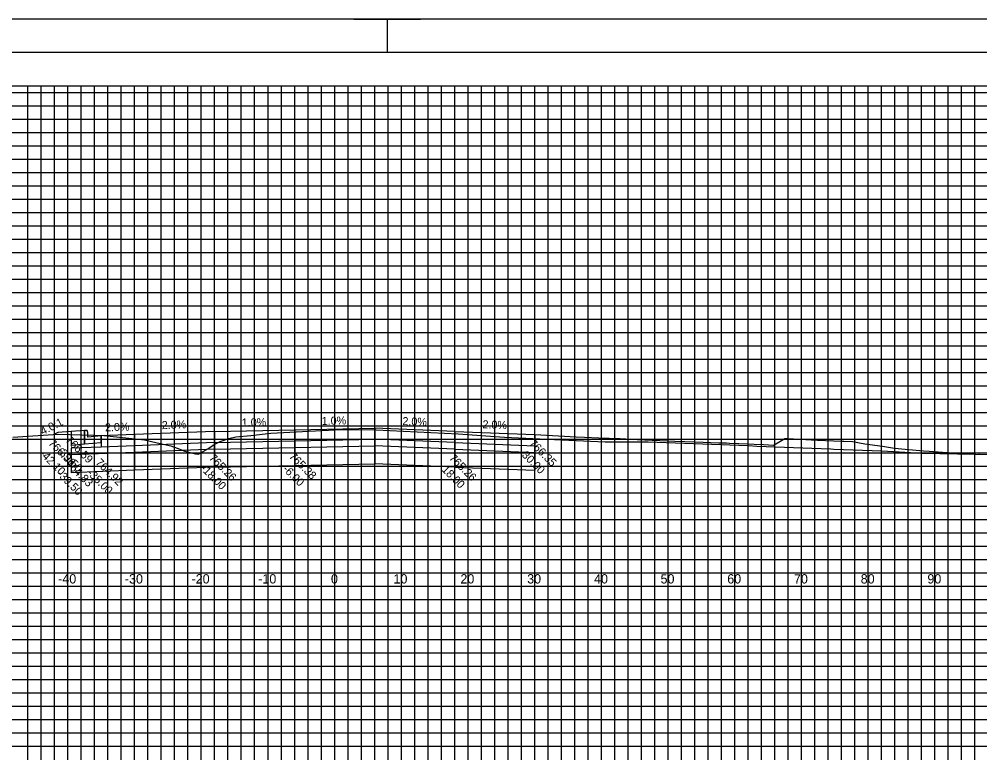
# Model space of a CAD drawing. Extents: x 578243 to 601557, y 174899 to 175559.
# Drawn here: x 601332.5 to 601476.6, y 175448.8 to 175558.8 of the extents above; entities that cross this region are included whole.
import ezdxf

# ---------------------------------------------------------------- set-up
doc = ezdxf.new("R2010")
doc.units = 0
for name, color, linetype in [('E_PROF_Grid', 7, 'Continuous'), ('E_PROF_GridMin', 7, 'Continuous'), ('P_CRDR_Label', 7, 'Continuous'), ('P_CRDR_Link', 7, 'Continuous'), ('P_E_XS_Ground', 7, 'Continuous'), ('P_SURF_Final_Top', 7, 'Continuous'), ('P_XS_Text', 7, 'Continuous'), ('PLT_Sheet_Border', 7, 'Continuous'), ('PLT_Sheet_Info', 7, 'Continuous')]:
    doc.layers.add(name, color=color, linetype=linetype)

msp = doc.modelspace()

# ---------------------------------------------------------------- linework, layer by layer
at = {"layer": 'E_PROF_Grid'}
for p, q in [((601339.84, 175353.8), (601339.84, 175548.8)), ((601349.84, 175353.8), (601349.84, 175548.8)), ((601359.84, 175353.8), (601359.84, 175548.8)), ((601369.84, 175353.8), (601369.84, 175548.8)), ((601379.84, 175353.8), (601379.84, 175548.8)), ((601389.84, 175353.8), (601389.84, 175548.8)), ((601399.84, 175353.8), (601399.84, 175548.8)), ((601409.84, 175353.8), (601409.84, 175548.8)), ((601419.84, 175353.8), (601419.84, 175548.8)), ((601429.84, 175353.8), (601429.84, 175548.8)), ((601439.84, 175353.8), (601439.84, 175548.8)), ((601449.84, 175353.8), (601449.84, 175548.8)), ((601459.84, 175353.8), (601459.84, 175548.8)), ((601469.84, 175353.8), (601469.84, 175548.8)), ((601229.84, 175543.8), (601544.84, 175543.8)), ((601229.84, 175533.8), (601544.84, 175533.8)), ((601229.84, 175523.8), (601544.84, 175523.8)), ((601229.84, 175513.8), (601544.84, 175513.8)), ((601229.84, 175503.8), (601544.84, 175503.8)), ((601229.84, 175493.8), (601544.84, 175493.8)), ((601229.84, 175483.8), (601544.84, 175483.8)), ((601229.84, 175473.8), (601544.84, 175473.8)), ((601229.84, 175463.8), (601544.84, 175463.8)), ((601229.84, 175453.8), (601544.84, 175453.8))]:
    msp.add_line(p, q, dxfattribs=at)
at = {"layer": 'E_PROF_GridMin'}
for p, q in [((601333.84, 175353.8), (601333.84, 175548.8)), ((601335.84, 175353.8), (601335.84, 175548.8)), ((601337.84, 175353.8), (601337.84, 175548.8)), ((601341.84, 175353.8), (601341.84, 175548.8)), ((601343.84, 175353.8), (601343.84, 175548.8)), ((601345.84, 175353.8), (601345.84, 175548.8)), ((601347.84, 175353.8), (601347.84, 175548.8)), ((601351.84, 175353.8), (601351.84, 175548.8)), ((601353.84, 175353.8), (601353.84, 175548.8)), ((601355.84, 175353.8), (601355.84, 175548.8)), ((601357.84, 175353.8), (601357.84, 175548.8)), ((601361.84, 175353.8), (601361.84, 175548.8)), ((601363.84, 175353.8), (601363.84, 175548.8)), ((601365.84, 175353.8), (601365.84, 175548.8)), ((601367.84, 175353.8), (601367.84, 175548.8)), ((601371.84, 175353.8), (601371.84, 175548.8)), ((601373.84, 175353.8), (601373.84, 175548.8)), ((601375.84, 175353.8), (601375.84, 175548.8)), ((601377.84, 175353.8), (601377.84, 175548.8)), ((601381.84, 175353.8), (601381.84, 175548.8)), ((601383.84, 175353.8), (601383.84, 175548.8)), ((601385.84, 175353.8), (601385.84, 175548.8)), ((601387.84, 175353.8), (601387.84, 175548.8)), ((601391.84, 175353.8), (601391.84, 175548.8)), ((601393.84, 175353.8), (601393.84, 175548.8)), ((601395.84, 175353.8), (601395.84, 175548.8)), ((601397.84, 175353.8), (601397.84, 175548.8)), ((601401.84, 175353.8), (601401.84, 175548.8)), ((601403.84, 175353.8), (601403.84, 175548.8)), ((601405.84, 175353.8), (601405.84, 175548.8)), ((601407.84, 175353.8), (601407.84, 175548.8)), ((601411.84, 175353.8), (601411.84, 175548.8)), ((601413.84, 175353.8), (601413.84, 175548.8)), ((601415.84, 175353.8), (601415.84, 175548.8)), ((601417.84, 175353.8), (601417.84, 175548.8)), ((601421.84, 175353.8), (601421.84, 175548.8)), ((601423.84, 175353.8), (601423.84, 175548.8)), ((601425.84, 175353.8), (601425.84, 175548.8)), ((601427.84, 175353.8), (601427.84, 175548.8)), ((601431.84, 175353.8), (601431.84, 175548.8)), ((601433.84, 175353.8), (601433.84, 175548.8)), ((601435.84, 175353.8), (601435.84, 175548.8)), ((601437.84, 175353.8), (601437.84, 175548.8)), ((601441.84, 175353.8), (601441.84, 175548.8)), ((601443.84, 175353.8), (601443.84, 175548.8)), ((601445.84, 175353.8), (601445.84, 175548.8)), ((601447.84, 175353.8), (601447.84, 175548.8)), ((601451.84, 175353.8), (601451.84, 175548.8)), ((601453.84, 175353.8), (601453.84, 175548.8)), ((601455.84, 175353.8), (601455.84, 175548.8)), ((601457.84, 175353.8), (601457.84, 175548.8)), ((601461.84, 175353.8), (601461.84, 175548.8)), ((601463.84, 175353.8), (601463.84, 175548.8)), ((601465.84, 175353.8), (601465.84, 175548.8)), ((601467.84, 175353.8), (601467.84, 175548.8)), ((601471.84, 175353.8), (601471.84, 175548.8)), ((601473.84, 175353.8), (601473.84, 175548.8)), ((601475.84, 175353.8), (601475.84, 175548.8)), ((601229.84, 175547.8), (601544.84, 175547.8)), ((601229.84, 175545.8), (601544.84, 175545.8)), ((601229.84, 175541.8), (601544.84, 175541.8)), ((601229.84, 175539.8), (601544.84, 175539.8)), ((601229.84, 175537.8), (601544.84, 175537.8)), ((601229.84, 175535.8), (601544.84, 175535.8)), ((601229.84, 175531.8), (601544.84, 175531.8)), ((601229.84, 175529.8), (601544.84, 175529.8)), ((601229.84, 175527.8), (601544.84, 175527.8)), ((601229.84, 175525.8), (601544.84, 175525.8)), ((601229.84, 175521.8), (601544.84, 175521.8)), ((601229.84, 175519.8), (601544.84, 175519.8)), ((601229.84, 175517.8), (601544.84, 175517.8)), ((601229.84, 175515.8), (601544.84, 175515.8)), ((601229.84, 175511.8), (601544.84, 175511.8)), ((601229.84, 175509.8), (601544.84, 175509.8)), ((601229.84, 175507.8), (601544.84, 175507.8)), ((601229.84, 175505.8), (601544.84, 175505.8)), ((601229.84, 175501.8), (601544.84, 175501.8)), ((601229.84, 175499.8), (601544.84, 175499.8)), ((601229.84, 175497.8), (601544.84, 175497.8)), ((601229.84, 175495.8), (601544.84, 175495.8)), ((601229.84, 175491.8), (601544.84, 175491.8)), ((601229.84, 175489.8), (601544.84, 175489.8)), ((601229.84, 175487.8), (601544.84, 175487.8)), ((601229.84, 175485.8), (601544.84, 175485.8)), ((601229.84, 175481.8), (601544.84, 175481.8)), ((601229.84, 175479.8), (601544.84, 175479.8)), ((601229.84, 175477.8), (601544.84, 175477.8)), ((601229.84, 175475.8), (601544.84, 175475.8)), ((601229.84, 175471.8), (601544.84, 175471.8)), ((601229.84, 175469.8), (601544.84, 175469.8)), ((601229.84, 175467.8), (601544.84, 175467.8)), ((601229.84, 175465.8), (601544.84, 175465.8)), ((601229.84, 175461.8), (601544.84, 175461.8)), ((601229.84, 175459.8), (601544.84, 175459.8)), ((601229.84, 175457.8), (601544.84, 175457.8)), ((601229.84, 175455.8), (601544.84, 175455.8)), ((601229.84, 175451.8), (601544.84, 175451.8)), ((601229.84, 175449.8), (601544.84, 175449.8))]:
    msp.add_line(p, q, dxfattribs=at)
at = {"layer": 'P_CRDR_Link'}
for points in [[(601338.34, 175496.82), (601337.73, 175496.52)], [(601338.34, 175496.82), (601337.73, 175496.52)], [(601340.34, 175496.98), (601338.34, 175496.82)], [(601340.34, 175496.98), (601338.34, 175496.82)], [(601342.34, 175497.14), (601340.34, 175496.98)], [(601340.34, 175496.98), (601340.34, 175494.94)], [(601340.34, 175496.98), (601340.34, 175494.94)], [(601340.34, 175496.98), (601340.34, 175494.94)], [(601342.66, 175497.14), (601342.34, 175497.14)], [(601342.66, 175497.14), (601342.34, 175497.14)], [(601342.34, 175497.14), (601342.34, 175495.1)], [(601342.34, 175495.1), (601342.34, 175497.14)], [(601342.74, 175497.1), (601342.66, 175497.14)], [(601342.74, 175497.1), (601342.66, 175497.14)], [(601342.8, 175496.98), (601342.74, 175497.1)], [(601342.8, 175496.98), (601342.74, 175497.1)], [(601342.82, 175496.82), (601342.8, 175496.98)], [(601342.82, 175496.82), (601342.8, 175496.98)], [(601342.84, 175496.14), (601342.82, 175496.82)], [(601342.84, 175496.14), (601342.82, 175496.82)], [(601344.84, 175496.3), (601342.84, 175496.14)], [(601344.84, 175496.3), (601342.84, 175496.14)], [(601349.84, 175496.5), (601344.84, 175496.3)], [(601344.84, 175496.3), (601344.84, 175494.64)], [(601344.84, 175495.3), (601344.84, 175496.3)], [(601361.84, 175496.98), (601349.84, 175496.5)], [(601349.84, 175496.5), (601349.84, 175494.84)], [(601349.84, 175496.5), (601349.84, 175494.84)], [(601361.84, 175496.98), (601373.84, 175497.22)], [(601361.84, 175496.98), (601361.84, 175495.32)], [(601361.84, 175496.98), (601361.84, 175495.32)], [(601373.84, 175497.22), (601385.84, 175497.46)], [(601373.84, 175497.22), (601373.84, 175495.56)], [(601373.84, 175497.22), (601373.84, 175495.56)], [(601385.84, 175497.46), (601385.84, 175495.8)], [(601397.84, 175496.98), (601385.84, 175497.46)], [(601385.84, 175497.46), (601385.84, 175495.8)], [(601397.84, 175496.98), (601409.84, 175496.5)], [(601397.84, 175496.98), (601397.84, 175495.32)], [(601397.84, 175496.98), (601397.84, 175495.32)], [(601409.84, 175496.5), (601409.84, 175494.84)], [(601340.34, 175494.94), (601342.34, 175495.1)], [(601342.34, 175495.1), (601344.84, 175495.3)], [(601342.34, 175495.1), (601344.84, 175495.3)], [(601349.84, 175494.84), (601344.84, 175494.64)], [(601361.84, 175495.32), (601349.84, 175494.84)], [(601349.84, 175494.84), (601349.84, 175493.84)], [(601349.84, 175494.84), (601349.84, 175493.84)], [(601361.84, 175495.32), (601373.84, 175495.56)], [(601361.84, 175495.32), (601361.84, 175494.32)], [(601361.84, 175495.32), (601361.84, 175494.32)], [(601373.84, 175495.56), (601385.84, 175495.8)], [(601373.84, 175495.56), (601373.84, 175494.56)], [(601373.84, 175495.56), (601373.84, 175494.56)], [(601373.84, 175494.56), (601385.84, 175494.8)], [(601385.84, 175495.8), (601385.84, 175494.8)], [(601397.84, 175495.32), (601385.84, 175495.8)], [(601385.84, 175495.8), (601385.84, 175494.8)], [(601385.84, 175494.8), (601385.84, 175492.13)], [(601397.84, 175494.32), (601385.84, 175494.8)], [(601385.84, 175494.8), (601385.84, 175492.13)], [(601397.84, 175495.32), (601409.84, 175494.84)], [(601397.84, 175495.32), (601397.84, 175494.32)], [(601397.84, 175495.32), (601397.84, 175494.32)], [(601409.84, 175494.84), (601409.84, 175493.84)], [(601344.84, 175494.64), (601340.34, 175494.46)], [(601340.34, 175494.46), (601340.34, 175493.46)], [(601349.84, 175493.84), (601340.34, 175493.46)], [(601340.34, 175493.46), (601340.34, 175490.79)], [(601361.84, 175494.32), (601349.84, 175493.84)], [(601349.84, 175493.84), (601349.84, 175491.17)], [(601349.84, 175493.84), (601349.84, 175491.17)], [(601361.84, 175494.32), (601373.84, 175494.56)], [(601361.84, 175494.32), (601361.84, 175491.65)], [(601361.84, 175494.32), (601361.84, 175491.65)], [(601373.84, 175494.56), (601373.84, 175491.89)], [(601373.84, 175494.56), (601373.84, 175491.89)], [(601397.84, 175494.32), (601409.84, 175493.84)], [(601397.84, 175494.32), (601397.84, 175491.65)], [(601397.84, 175494.32), (601397.84, 175491.65)], [(601409.84, 175493.84), (601409.84, 175491.17)], [(601373.84, 175491.89), (601385.84, 175492.13)], [(601397.84, 175491.65), (601385.84, 175492.13)], [(601349.84, 175491.17), (601340.34, 175490.79)], [(601361.84, 175491.65), (601349.84, 175491.17)], [(601361.84, 175491.65), (601373.84, 175491.89)], [(601397.84, 175491.65), (601409.84, 175491.17)]]:
    msp.add_lwpolyline(points, dxfattribs=at)
at = {"layer": 'P_E_XS_Ground'}
msp.add_lwpolyline([(601331.57, 175496.14), (601338.37, 175496.56), (601343.66, 175496.42), (601345.2, 175496.37), (601351.33, 175495.74), (601353.21, 175495.28), (601355.28, 175494.83), (601356.23, 175494.5), (601357.35, 175494.04), (601358.96, 175493.64), (601359.4, 175493.56), (601359.78, 175493.78), (601360.81, 175494.4), (601361.78, 175495.03), (601362.65, 175495.48), (601363.97, 175495.91), (601365.04, 175496.19), (601367.26, 175496.38), (601370.26, 175496.7), (601375.01, 175496.99), (601379.84, 175497.22), (601381.31, 175497.29), (601381.31, 175497.29), (601386.06, 175497.23), (601398.37, 175496.61), (601405.31, 175496.14), (601410.6, 175495.89), (601420.38, 175495.43), (601426.84, 175495.4), (601440.44, 175494.93), (601441.89, 175494.86), (601443.14, 175494.79), (601452.77, 175494.41), (601454.22, 175494.36), (601454.68, 175494.34), (601461.86, 175494.07), (601467.93, 175493.73), (601481.24, 175493.49)], dxfattribs=at)
at = {"layer": 'P_SURF_Final_Top'}
msp.add_lwpolyline([(601409.84, 175496.5), (601416.03, 175496.19), (601417.29, 175496.14), (601419.42, 175496.03), (601422.61, 175495.9), (601422.64, 175495.9), (601422.66, 175495.9), (601425.21, 175495.79), (601430.85, 175495.53), (601433.89, 175495.42), (601437.44, 175495.29), (601438.58, 175495.25), (601439.02, 175495.24), (601441.85, 175495.14), (601442.73, 175495.09), (601444.11, 175495.01), (601445.62, 175494.94), (601446.58, 175495.49), (601447.33, 175495.92), (601447.47, 175495.91), (601447.67, 175495.91), (601449.59, 175495.81), (601452.22, 175495.69), (601454.62, 175495.58), (601455.97, 175495.52), (601456.17, 175495.51), (601456.17, 175495.51), (601456.18, 175495.51), (601456.18, 175495.51), (601456.19, 175495.51), (601457.49, 175495.46), (601459.32, 175495.14), (601462, 175494.76), (601463.79, 175494.5), (601465.39, 175494.34), (601468.1, 175494.06), (601468.95, 175494.01), (601472.31, 175493.8), (601476.4, 175493.72), (601476.53, 175493.72)], dxfattribs=at)
at = {"layer": 'PLT_Sheet_Border'}
for points in [[(601217.19, 175338.8), (601557.19, 175338.8), (601557.19, 175558.8), (601217.19, 175558.8)], [(601219.59, 175343.8), (601550.59, 175343.8), (601550.59, 175553.8), (601219.59, 175553.8)]]:
    msp.add_lwpolyline(points, close=True, dxfattribs=at)
at = {"layer": 'PLT_Sheet_Info'}
for p, q in [((601382.69, 175558.8), (601392.69, 175558.8)), ((601387.69, 175558.8), (601387.69, 175553.8)), ((601229.84, 175548.8), (601544.84, 175548.8))]:
    msp.add_line(p, q, dxfattribs=at)

# ---------------------------------------------------------------- texts
at = {"layer": 'P_CRDR_Label'}
for s, rotation, p in [('1.0%', 1.1458, (601377.91, 175497.96)), ('2.0%', 357.7094, (601389.98, 175497.95)), ('4.0:1', 26.5651, (601336.06, 175496.4)), ('2.0%', 2.2906, (601345.43, 175496.98)), ('2.0%', 2.2906, (601353.93, 175497.32)), ('1.0%', 1.1458, (601365.92, 175497.72)), ('2.0%', 357.7094, (601401.98, 175497.47)), ('766.59', 315, (601339.41, 175495.57)), ('766.36', 315, (601336.81, 175495.11)), ('766.36', 315, (601336.81, 175495.11)), ('766.35', 315, (601408.91, 175495.09)), ('-42.10', 315, (601335.52, 175493.54)), ('-42.10', 315, (601335.52, 175493.54)), ('-39.50', 315, (601338.12, 175494.01)), ('765.26', 315, (601360.91, 175492.9)), ('765.26', 315, (601360.91, 175492.9)), ('765.38', 315, (601372.91, 175493.14)), ('765.26', 315, (601396.91, 175492.9)), ('765.26', 315, (601396.91, 175492.9)), ('30.00', 315, (601407.81, 175493.35)), ('764.83', 315, (601339.41, 175492.04)), ('764.92', 315, (601343.91, 175492.22)), ('-39.50', 315, (601338.11, 175490.5)), ('-35.00', 315, (601342.62, 175490.67)), ('-18.00', 315, (601359.63, 175491.34)), ('-18.00', 315, (601359.63, 175491.34)), ('-6.00', 315, (601371.97, 175491.24)), ('18.00', 315, (601395.8, 175491.17)), ('18.00', 315, (601395.8, 175491.17))]:
    msp.add_text(s, height=1.2, rotation=rotation, dxfattribs=at).set_placement(p)
at = {"layer": 'P_XS_Text'}
for s, p in [('-40', (601338.38, 175474.18)), ('-30', (601348.38, 175474.18)), ('-20', (601358.38, 175474.18)), ('-10', (601368.38, 175474.18)), ('0', (601379.28, 175474.18)), ('0', (601379.28, 175474.18)), ('10', (601388.66, 175474.18)), ('20', (601398.69, 175474.18)), ('30', (601408.7, 175474.18)), ('40', (601418.73, 175474.18)), ('50', (601428.7, 175474.18)), ('60', (601438.7, 175474.18)), ('70', (601448.7, 175474.18)), ('80', (601458.71, 175474.18)), ('90', (601468.71, 175474.18))]:
    msp.add_text(s, height=1.4, rotation=360, dxfattribs=at).set_placement(p)

doc.saveas('drawing.dxf')
